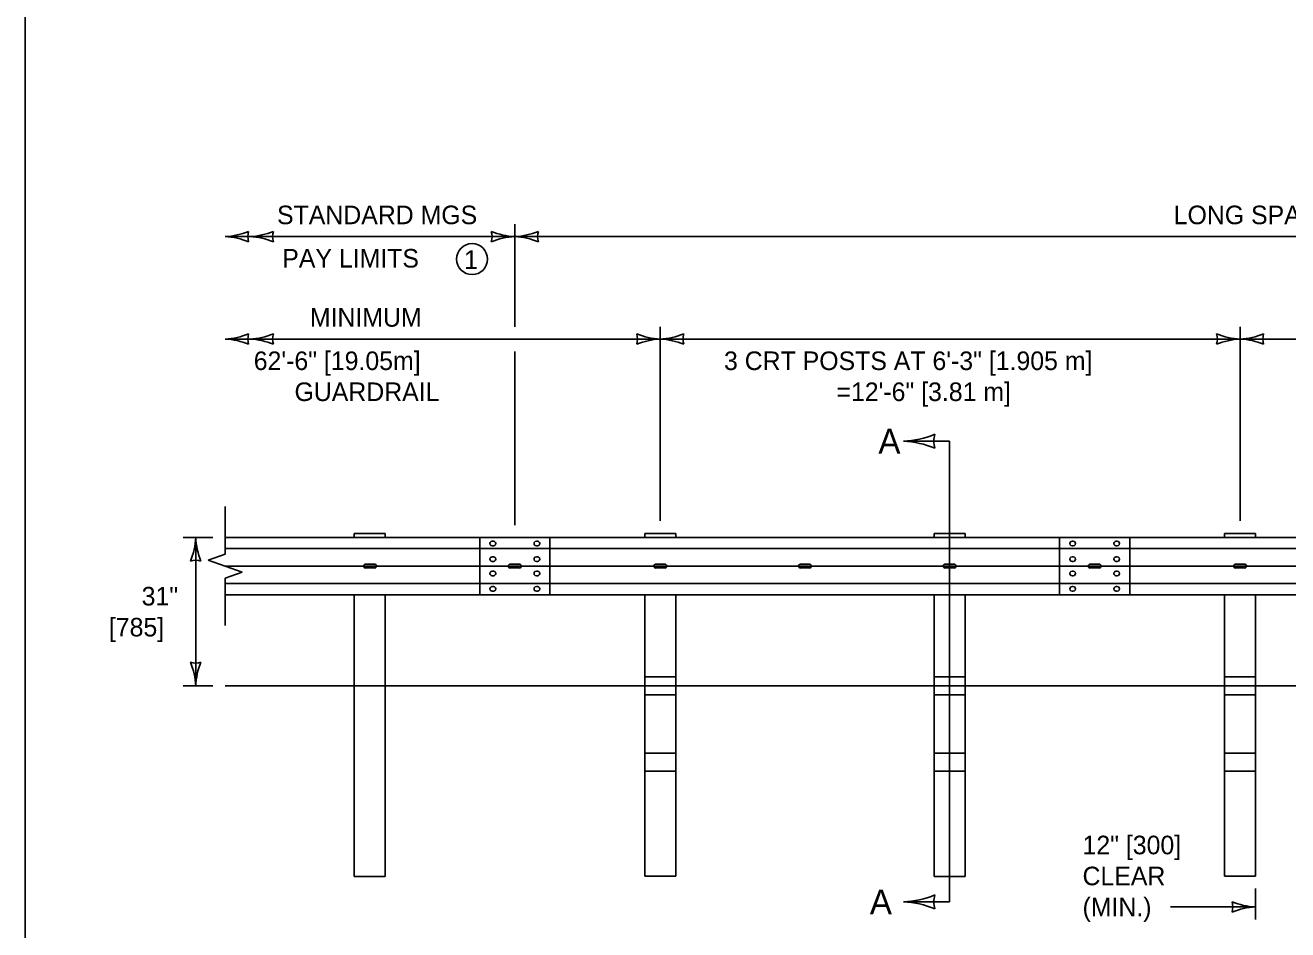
# Model space of a CAD drawing. Extents: x 49991.4 to 50021, y 49987.6 to 50011.4.
# Drawn here: x 49999.384 to 50003.461, y 49993.16 to 49996.08 of the extents above; entities that cross this region are included whole.
import ezdxf

# ---------------------------------------------------------------- set-up
doc = ezdxf.new("R2010")
doc.units = 0
for name, color, linetype in [('Level 1', 7, 'Continuous'), ('Level 2', 7, 'Continuous'), ('Level 3', 7, 'Continuous'), ('Level 4', 7, 'Continuous'), ('Level 5', 7, 'Continuous'), ('Level 6', 7, 'Continuous')]:
    doc.layers.add(name, color=color, linetype=linetype)

msp = doc.modelspace()

# ---------------------------------------------------------------- linework, layer by layer
at = {"layer": 'Level 1'}
for p, q in [((50000.0289, 49994.4263), (50010.4985, 49994.4263)), ((50000.4461, 49994.4395), (50000.4461, 49994.4263)), ((50000.4461, 49994.4395), (50000.5461, 49994.4395)), ((50000.5461, 49994.4263), (50000.5461, 49994.4395)), ((50000.8512, 49994.241), (50000.8512, 49994.4256)), ((50000.8954, 49994.414), (50000.8918, 49994.414)), ((50001.0376, 49994.414), (50001.034, 49994.414)), ((50001.3842, 49994.4263), (50001.3842, 49994.4395)), ((50001.3842, 49994.4395), (50001.4841, 49994.4395)), ((50001.4841, 49994.4263), (50001.4841, 49994.4395)), ((50002.3186, 49994.4395), (50002.3186, 49994.4263)), ((50002.3186, 49994.4395), (50002.4186, 49994.4395)), ((50002.4186, 49994.4263), (50002.4186, 49994.4395)), ((50002.7236, 49994.241), (50002.7236, 49994.4256)), ((50002.7678, 49994.414), (50002.7642, 49994.414)), ((50002.9101, 49994.414), (50002.9065, 49994.414)), ((50003.2567, 49994.4263), (50003.2567, 49994.4396)), ((50003.2567, 49994.4396), (50003.3566, 49994.4396)), ((50003.3566, 49994.4263), (50003.3566, 49994.4396)), ((50000.0289, 49994.3903), (50010.4985, 49994.3903)), ((50000.8954, 49994.3989), (50000.8918, 49994.3989)), ((50000.8954, 49994.3641), (50000.8918, 49994.3641)), ((50001.0376, 49994.3989), (50001.034, 49994.3989)), ((50001.0376, 49994.3641), (50001.034, 49994.3641)), ((50002.7678, 49994.3989), (50002.7642, 49994.3989)), ((50002.7678, 49994.3641), (50002.7642, 49994.3641)), ((50002.9101, 49994.3989), (50002.9065, 49994.3989)), ((50002.9101, 49994.3641), (50002.9065, 49994.3641)), ((50000.4826, 49994.3403), (50000.5117, 49994.3403)), ((50000.4826, 49994.3278), (50000.5117, 49994.3278)), ((50000.8954, 49994.349), (50000.8918, 49994.349)), ((50000.9498, 49994.3403), (50000.979, 49994.3403)), ((50000.9498, 49994.3278), (50000.979, 49994.3278)), ((50001.0376, 49994.349), (50001.034, 49994.349)), ((50001.4196, 49994.3403), (50001.4487, 49994.3403)), ((50001.4196, 49994.3278), (50001.4487, 49994.3278)), ((50001.8868, 49994.3403), (50001.916, 49994.3403)), ((50001.8868, 49994.3278), (50001.916, 49994.3278)), ((50002.354, 49994.3403), (50002.3832, 49994.3403)), ((50002.354, 49994.3278), (50002.3832, 49994.3278)), ((50002.7678, 49994.349), (50002.7642, 49994.349)), ((50002.8223, 49994.3403), (50002.8514, 49994.3403)), ((50002.8223, 49994.3278), (50002.8514, 49994.3278)), ((50002.9101, 49994.349), (50002.9065, 49994.349)), ((50003.292, 49994.3403), (50003.3212, 49994.3403)), ((50003.292, 49994.3278), (50003.3212, 49994.3278)), ((50000.8954, 49994.3176), (50000.8918, 49994.3176)), ((50000.8954, 49994.3025), (50000.8918, 49994.3025)), ((50001.0376, 49994.3176), (50001.034, 49994.3176)), ((50001.0376, 49994.3025), (50001.034, 49994.3025)), ((50002.7678, 49994.3176), (50002.7642, 49994.3176)), ((50002.7678, 49994.3025), (50002.7642, 49994.3025)), ((50002.9101, 49994.3176), (50002.9065, 49994.3176)), ((50002.9101, 49994.3025), (50002.9065, 49994.3025)), ((50000.0289, 49994.2777), (50010.4985, 49994.2777)), ((50000.0289, 49994.2417), (50010.4985, 49994.2417)), ((50000.4461, 49993.9473), (50000.4461, 49994.2417)), ((50000.5461, 49993.9473), (50000.5461, 49994.2417)), ((50000.8954, 49994.2677), (50000.8918, 49994.2677)), ((50000.8954, 49994.2526), (50000.8918, 49994.2526)), ((50001.0376, 49994.2677), (50001.034, 49994.2677)), ((50001.0376, 49994.2526), (50001.034, 49994.2526)), ((50001.3841, 49993.9473), (50001.3841, 49994.2417)), ((50001.4841, 49993.9473), (50001.4841, 49994.2417)), ((50002.3186, 49993.9473), (50002.3186, 49994.2417)), ((50002.4185, 49993.9473), (50002.4185, 49994.2417)), ((50002.7678, 49994.2677), (50002.7642, 49994.2677)), ((50002.7678, 49994.2526), (50002.7642, 49994.2526)), ((50002.9101, 49994.2677), (50002.9065, 49994.2677)), ((50002.9101, 49994.2526), (50002.9065, 49994.2526)), ((50003.2566, 49993.9473), (50003.2566, 49994.2417)), ((50003.3566, 49993.9473), (50003.3566, 49994.2417)), ((50010.4985, 49993.9473), (50000.0289, 49993.9473))]:
    msp.add_line(p, q, dxfattribs=at)
msp.add_lwpolyline([(49999.3835, 49998.9992), (50016.7501, 49998.9992), (50016.7501, 49987.7988), (49999.3835, 49987.7988)], close=True, dxfattribs=at)
for centre, start, end in [((50000.4826, 49994.334), 90, 180), ((50000.4826, 49994.334), 180, 270), ((50000.5117, 49994.334), 360, 90), ((50000.5117, 49994.334), 270, 0), ((50000.9498, 49994.334), 90, 180), ((50000.9498, 49994.334), 180, 270), ((50000.979, 49994.334), 360, 90), ((50000.979, 49994.334), 270, 0), ((50001.4196, 49994.334), 90, 180), ((50001.4196, 49994.334), 180, 270), ((50001.4487, 49994.334), 360, 90), ((50001.4487, 49994.334), 270, 0), ((50001.8868, 49994.334), 90, 180), ((50001.8868, 49994.334), 180, 270), ((50001.916, 49994.334), 360, 90), ((50001.916, 49994.334), 270, 0), ((50002.354, 49994.334), 90, 180), ((50002.354, 49994.334), 180, 270), ((50002.3832, 49994.334), 360, 90), ((50002.3832, 49994.334), 270, 0), ((50002.8223, 49994.334), 90, 180), ((50002.8223, 49994.334), 180, 270), ((50002.8514, 49994.334), 360, 90), ((50002.8514, 49994.334), 270, 0), ((50003.292, 49994.334), 90, 180), ((50003.292, 49994.334), 180, 270), ((50003.3212, 49994.334), 360, 90), ((50003.3212, 49994.334), 270, 0)]:
    msp.add_arc(centre, 0.00625, start, end, dxfattribs=at)
for centre, start_param, end_param in [((50000.8918, 49994.4065), 1.570796, 4.712389), ((50000.8954, 49994.4065), 4.712389, 7.853982), ((50001.034, 49994.4065), 1.570796, 4.712389), ((50001.0376, 49994.4065), 4.712389, 7.853982), ((50002.7642, 49994.4065), 1.570796, 4.712389), ((50002.7678, 49994.4065), 4.712389, 7.853982), ((50002.9065, 49994.4065), 1.570796, 4.712389), ((50002.9101, 49994.4065), 4.712389, 7.853982), ((50000.8918, 49994.3566), 1.570796, 4.712389), ((50000.8954, 49994.3566), 4.712389, 7.853982), ((50001.034, 49994.3566), 1.570796, 4.712389), ((50001.0376, 49994.3566), 4.712389, 7.853982), ((50002.7642, 49994.3566), 1.570796, 4.712389), ((50002.7678, 49994.3566), 4.712389, 7.853982), ((50002.9065, 49994.3566), 1.570796, 4.712389), ((50002.9101, 49994.3566), 4.712389, 7.853982), ((50000.8918, 49994.3101), 1.570796, 4.712389), ((50000.8954, 49994.3101), 4.712389, 7.853982), ((50001.034, 49994.3101), 1.570796, 4.712389), ((50001.0376, 49994.3101), 4.712389, 7.853982), ((50002.7642, 49994.3101), 1.570796, 4.712389), ((50002.7678, 49994.3101), 4.712389, 7.853982), ((50002.9065, 49994.3101), 1.570796, 4.712389), ((50002.9101, 49994.3101), 4.712389, 7.853982), ((50000.8918, 49994.2602), 1.570796, 4.712389), ((50000.8954, 49994.2602), 4.712389, 7.853982), ((50001.034, 49994.2602), 1.570796, 4.712389), ((50001.0376, 49994.2602), 4.712389, 7.853982), ((50002.7642, 49994.2602), 1.570796, 4.712389), ((50002.7678, 49994.2602), 4.712389, 7.853982), ((50002.9065, 49994.2602), 1.570796, 4.712389), ((50002.9101, 49994.2602), 4.712389, 7.853982)]:
    msp.add_ellipse(centre, major_axis=(0.00756, 0), ratio=0.998676, start_param=start_param, end_param=end_param, dxfattribs=at)
at = {"layer": 'Level 2'}
msp.add_circle((50000.8264, 49995.3247), 0.05, dxfattribs=at)
at = {"layer": 'Level 3'}
for p, q in [((50000.9644, 49995.1067), (50000.9644, 49995.4375)), ((50008.4543, 49995.3975), (50000.0289, 49995.3975)), ((50001.4342, 49994.4796), (50001.4342, 49995.1067)), ((50003.3066, 49994.4796), (50003.3066, 49995.1067)), ((50001.4342, 49995.0667), (50000.0289, 49995.0667)), ((50003.3066, 49995.0667), (50001.4342, 49995.0667)), ((50006.11, 49995.0667), (50003.3066, 49995.0667)), ((50000.9644, 49994.4662), (50000.9644, 49995.0267)), ((49999.894, 49994.4263), (49999.9889, 49994.4263)), ((49999.934, 49993.9473), (49999.934, 49994.4263)), ((49999.894, 49993.9473), (49999.9889, 49993.9473)), ((50003.3566, 49993.2932), (50003.3566, 49993.1937)), ((50003.3566, 49993.2337), (50003.0816, 49993.2337))]:
    msp.add_line(p, q, dxfattribs=at)
for centre, radius, start, end in [((50000.0174, 49995.6303), 0.233, 272.8273, 292.0772), ((50000.0197, 49995.1754), 0.2223, 67.456, 87.6395), ((50000.1571, 49995.3975), 0.0548, 162.1388, 197.8612), ((50000.0973, 49995.6303), 0.233, 272.8273, 292.0772), ((50000.0997, 49995.1754), 0.2223, 67.456, 87.6395), ((50000.237, 49995.3975), 0.0548, 162.1388, 197.8612), ((50000.9735, 49995.6197), 0.2223, 247.456, 267.6395), ((50000.8362, 49995.3975), 0.0548, 342.1388, 17.8612), ((50000.9759, 49995.1648), 0.233, 92.8273, 112.0772), ((50000.9529, 49995.6303), 0.233, 272.8273, 292.0772), ((50000.9552, 49995.1754), 0.2223, 67.456, 87.6395), ((50001.0926, 49995.3975), 0.0548, 162.1388, 197.8612), ((50000.0174, 49995.2995), 0.233, 272.8273, 292.0772), ((50000.0197, 49994.8446), 0.2223, 67.456, 87.6395), ((50000.1571, 49995.0667), 0.0548, 162.1388, 197.8612), ((50000.0973, 49995.2995), 0.233, 272.8273, 292.0772), ((50000.0997, 49994.8446), 0.2223, 67.456, 87.6395), ((50000.237, 49995.0667), 0.0548, 162.1388, 197.8612), ((50001.4433, 49995.2889), 0.2223, 247.456, 267.6395), ((50001.3059, 49995.0667), 0.0548, 342.1388, 17.8612), ((50001.4457, 49994.834), 0.233, 92.8273, 112.0772), ((50001.425, 49995.2889), 0.2223, 272.3605, 292.544), ((50001.4227, 49994.834), 0.233, 67.9228, 87.1727), ((50001.5624, 49995.0667), 0.0548, 162.1388, 197.8612), ((50003.3158, 49995.2889), 0.2223, 247.456, 267.6395), ((50003.1784, 49995.0667), 0.0548, 342.1388, 17.8612), ((50003.3181, 49994.834), 0.233, 92.8273, 112.0772), ((50003.2951, 49995.2995), 0.233, 272.8273, 292.0772), ((50003.2975, 49994.8446), 0.2223, 67.456, 87.6395), ((50003.4348, 49995.0667), 0.0548, 162.1388, 197.8612), ((50002.2073, 49995.0333), 0.2964, 272.3605, 292.544), ((50002.2041, 49994.4268), 0.3107, 67.9228, 87.1727), ((50002.3904, 49994.7371), 0.073, 162.1388, 197.8612), ((49999.7119, 49994.4355), 0.2223, 337.456, 357.6395), ((50000.1667, 49994.4378), 0.233, 182.8273, 202.0772), ((49999.934, 49994.2981), 0.0548, 72.1388, 107.8612), ((49999.934, 49994.0755), 0.0548, 252.1388, 287.8612), ((49999.7013, 49993.9358), 0.233, 2.8273, 22.0772), ((50000.1561, 49993.9382), 0.2223, 157.456, 177.6395), ((50002.2042, 49993.5603), 0.3107, 272.8273, 292.0772), ((50002.3905, 49993.25), 0.073, 162.1388, 197.8612), ((50002.2074, 49992.9538), 0.2964, 67.456, 87.6395), ((50003.3658, 49993.4559), 0.2223, 247.456, 267.6395), ((50003.2284, 49993.2337), 0.0548, 342.1388, 17.8612), ((50003.3681, 49993.001), 0.233, 92.8273, 112.0772)]:
    msp.add_arc(centre, radius, start, end, dxfattribs=at)
at = {"layer": 'Level 4'}
for p, q in [((50001.0776, 49994.241), (50001.0776, 49994.4256)), ((50002.9501, 49994.241), (50002.9501, 49994.4256)), ((50001.3842, 49993.9764), (50001.4841, 49993.9764)), ((50002.3186, 49993.9764), (50002.4185, 49993.9764)), ((50003.2567, 49993.9765), (50003.3566, 49993.9765)), ((50000.4461, 49993.9473), (50000.4461, 49993.332)), ((50000.5461, 49993.9473), (50000.5461, 49993.332)), ((50001.3841, 49993.9473), (50001.3841, 49993.3332)), ((50001.3842, 49993.9181), (50001.4841, 49993.9181)), ((50001.4841, 49993.9473), (50001.4841, 49993.3332)), ((50002.3186, 49993.9473), (50002.3186, 49993.332)), ((50002.3186, 49993.9181), (50002.4185, 49993.9181)), ((50002.4185, 49993.9473), (50002.4185, 49993.332)), ((50003.2566, 49993.9473), (50003.2566, 49993.3332)), ((50003.2567, 49993.9182), (50003.3566, 49993.9182)), ((50003.3566, 49993.9473), (50003.3566, 49993.3332)), ((50001.3842, 49993.7303), (50001.4841, 49993.7303)), ((50002.3186, 49993.7303), (50002.4185, 49993.7303)), ((50003.2567, 49993.7304), (50003.3566, 49993.7304)), ((50001.3842, 49993.672), (50001.4841, 49993.672)), ((50002.3186, 49993.672), (50002.4185, 49993.672)), ((50003.2567, 49993.6721), (50003.3566, 49993.6721)), ((50000.5461, 49993.332), (50000.4461, 49993.332)), ((50001.4841, 49993.3332), (50001.3841, 49993.3332)), ((50002.4185, 49993.332), (50002.3186, 49993.332)), ((50003.3566, 49993.3332), (50003.2566, 49993.3332))]:
    msp.add_line(p, q, dxfattribs=at)
at = {"layer": 'Level 5'}
msp.add_line((50010.4985, 49994.334), (50000.0289, 49994.334), dxfattribs=at)
at = {"layer": 'Level 6'}
for p, q in [((50002.3685, 49994.7371), (50002.2195, 49994.7371)), ((50002.3686, 49993.25), (50002.3685, 49994.7371)), ((50000.0289, 49994.5263), (50000.0289, 49994.3729)), ((49999.974, 49994.3535), (50000.0289, 49994.3729)), ((49999.974, 49994.3535), (50000.0289, 49994.334)), ((50000.0289, 49994.334), (50000.0837, 49994.3146)), ((50000.0289, 49994.2951), (50000.0837, 49994.3146)), ((50000.0289, 49994.2951), (50000.0289, 49994.1417)), ((50002.2196, 49993.25), (50002.3686, 49993.25))]:
    msp.add_line(p, q, dxfattribs=at)

# ---------------------------------------------------------------- texts
at = {"layer": 'Level 2'}
for s, height, p in [('STANDARD MGS', 0.06, (50000.1966, 49995.4375)), ('LONG SPAN MGS GUARDRAIL PAY LIMITS 50\'-0" [15.24m]  OR 62\'-6" [19.05m] FOR 18\'-9" [5.715m] SPAN', 0.06, (50003.0923, 49995.4375)), ('PAY LIMITS', 0.06, (50000.2135, 49995.2976)), ('1', 0.06, (50000.8007, 49995.2933)), ('MINIMUM', 0.06, (50000.3026, 49995.1067)), (' 62\'-6" [19.05m]', 0.06, (50000.0991, 49994.9667)), ('3 CRT POSTS AT 6\'-3" [1.905 m]', 0.06, (50001.64, 49994.9667)), ('GUARDRAIL', 0.06, (50000.253, 49994.8667)), (' =12\'-6" [3.81 m] ', 0.06, (50001.9809, 49994.8667)), ('A', 0.0799, (50002.1386, 49994.6972)), ('31"', 0.06, (49999.7594, 49994.2068)), ('[785]', 0.06, (49999.6536, 49994.1068)), ('12" [300]', 0.06, (50002.7978, 49993.4037)), ('CLEAR', 0.06, (50002.7978, 49993.3037)), ('A', 0.0799, (50002.111, 49993.2101)), ('(MIN.)', 0.06, (50002.7978, 49993.2037))]:
    msp.add_text(s, height=height, dxfattribs=at).set_placement(p)

doc.saveas('drawing.dxf')
